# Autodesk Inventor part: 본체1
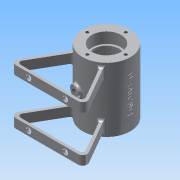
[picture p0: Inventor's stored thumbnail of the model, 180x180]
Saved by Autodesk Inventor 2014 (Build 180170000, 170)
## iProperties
Created: 2016-03
Part Number: 본체1
Material: 알루미늄 6061
Document SubType Name: Modeling
Designer: 406-16
Density: 2.71 g/cm^3
Appearance: 알루미늄 - 평지
Mass: 215.217 g
Surface Area: 337.503 cm^2
Volume: 79.416 cm^3
Author: 406-16
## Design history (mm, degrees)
sketch "스케치1"
  geometry: C1 r 26 at (0, 0); 1 further point
  constraints: 1 centre point, 1 coincident
  dimensions: "d0" = 52 diameter of C1
extrude "돌출1" new body sketch "스케치1" distance "d1" = 70; taper "d2" = 0 deg
sketch "스케치2"
  geometry: C1 r 26 at (0, 0) reference; C2 r 16 at (0, 0)
  constraints: 1 centre point, 1 coincident
  dimensions: "d3" = 32 diameter of C2
extrude "돌출2" cut sketch "스케치2" distance "d4" = 12; taper "d5" = 0 deg
sketch "스케치3"
  geometry: C1 r 16 at (0, 0) reference; C2 r 14 at (0, 0)
  constraints: 1 centre point, 1 coincident
  dimensions: "d6" = 28 diameter of C2
extrude "돌출3" cut sketch "스케치3" distance "d7" = 2; taper "d8" = 0 deg
sketch "스케치4"
  geometry: C1 r 26 at (0, 0) reference; C2 r 16 at (0, 0)
  constraints: 1 centre point, 1 coincident
  dimensions: "d9" = 32 diameter of C2
extrude "돌출4" cut sketch "스케치4" distance "d10" = 12; taper "d11" = 0 deg
sketch "스케치5"
  geometry: C1 r 16 at (0, 0) reference; C2 r 14 at (0, 0)
  constraints: 1 centre point, 1 coincident
  dimensions: "d12" = 28 diameter of C2
extrude "돌출5" cut sketch "스케치5" distance "d13" = 2; taper "d14" = 0 deg
node "작업 평면1"
sketch "스케치6"
  geometry: C1 r 21 at (0, 0); 1 further point
  constraints: 1 centre point, 1 coincident
  dimensions: "d16" = 42 diameter of C1
extrude "돌출6" cut sketch "스케치6" stored distance "d17" = 42; taper "d18" = 0 deg
node "작업 평면2"
sketch "스케치7"
  geometry: L1 (16.613, -20)-(38.264, -57.5); L2 (0, 0)-(0, -50.57); L3 (-16.613, -20)-(-38.264, -57.5); L4 (-33.934, -65)-(33.934, -65); L5 (14.015, -21.5)-(34.8, -57.5); L6 (32.202, -62)-(-32.202, -62); L7 (-34.8, -57.5)-(-14.015, -21.5); A1 r 5 centre (-33.934, -60) between (-38.264, -57.5) and (-33.934, -65); A2 r 5 centre (33.934, -60) between (33.934, -65) and (38.264, -57.5); A3 r 26 centre (0, 0) between (-16.613, -20) and (-14.183, -21.791); A4 r 26 centre (0, 0) between (14.183, -21.791) and (16.613, -20); A5 r 3 centre (-32.202, -59) between (-34.8, -57.5) and (-32.202, -62); A6 r 3 centre (32.202, -59) between (32.202, -62) and (34.8, -57.5); 3 further points
  constraints: 14 end point, 12 point on circle, 8 tangent, 6 centre point, 6 point on line, 2 symmetric about line, 1 coincident, 1 equal radius, 1 perpendicular, 1 vertical, 4 other
  dimensions: "d20" = 65 vertical distance of point (42.594, -65) point (0, 0); "d21" = 45 vertical distance of point (42.594, -65) L1.start; "d22" = 30 deg angle of L1 L2; "d23" = 3 distance between parallel lines of L7 L3; "d24" = 5 radius of A1; "d101" = 3 radius of A5; "d102" = 3 radius of A6; "d103" = 14.01517 distance from line of L5.start L2; "d104" = 29.67242 distance from line of L2.end L1; "d105" = 27.27499 distance from line of L7.end L1
extrude "돌출7" join sketch "스케치7" distance "d25" = 10; taper "d26" = 0 deg
node "작업 평면3"
sketch "스케치8"
  geometry: L1 (-26, 0)-(-26, -70) reference; L2 (-26, 0)-(26, 0) reference; C1 r 5 at (0, -35); 1 further point
  constraints: 1 centre point
  dimensions: "d28" = 10 diameter of C1; "d29" = 26 distance from line of C1.centre L1; "d30" = 35 distance from line of C1.centre L2
extrude "돌출8" join sketch "스케치8" stored distance "d31" = 3; taper "d32" = 0 deg
hole "구멍1" diameter "d35" = 5.188; stored, may be unused: countersink angle "d39" = 90 deg, drill point angle "d41" = 118 deg; dims "d33" = 10, "d34" = 10, "d36" = 20, "d37" = 4, "d38" = 2, "d40" = 25
sketch "스케치12"
  geometry: L1 (0, 21)-(0, 0); L2 (0, 0)-(21, 0); C1 r 26 at (0, 0) reference; A1 r 21 centre (0, 0) between (0, 21) and (21, 0)
  constraints: 4 end point, 2 point on circle, 1 centre point, 1 coincident, 1 perpendicular, 1 vertical
  dimensions: "d64" = 42 diameter of A1
hole "구멍3" sketch "스케치12" at (0, 21) diameter "d65" = 3.242; stored, may be unused: countersink angle "d69" = 90 deg, drill point angle "d71" = 118 deg; dims "d66" = 8, "d67" = 4, "d68" = 2, "d70" = 10
node "작업 평면5"
sketch "스케치13"
  geometry: L1 (26, 0)-(26, -70) reference; L2 (-26, 0)-(26, 0) reference; 2 further points
  constraints: 1 other
  dimensions: "d75" = 26 distance from line of point (0, -35) L1; "d76" = 35 distance from line of point (0, -35) L2
feature "엠보싱1" sketch "스케치13" dims "d77" = 0.5, "d78" = 0
sketch "스케치14"
  geometry: L1 (0, 0)-(-7.506, -28.012); L2 (0, 0)-(0, -34.845)
  constraints: 4 end point, 1 vertical
  dimensions: "d79" = 29 distance of L1.end L1.start; "d80" = 15 deg angle of L2 L1; "d81" = 9.01864 distance from line of L2.end L1
node "작업 평면6"
sketch "스케치15"
  geometry: L1 (-26, 35)-(-26, -35) reference; L2 (-26, 35)-(26, 35) reference; C1 r 6 at (0, 0); 1 further point
  constraints: 1 centre point
  dimensions: "d82" = 12 diameter of C1; "d84" = 26 distance from line of C1.centre L1; "d85" = 35 distance from line of C1.centre L2
extrude "돌출11" join sketch "스케치15" stored distance "d86" = 3; taper "d87" = 0 deg
hole "구멍4" diameter "d90" = 5.188; stored, may be unused: countersink angle "d94" = 90 deg, drill point angle "d96" = 118 deg; dims "d88" = 10, "d89" = 10, "d91" = 20, "d92" = 4, "d93" = 2, "d95" = 25
fillet "모깎기1" dims "d97" = 2
fillet "모깎기2" dims "d98" = 3
fillet "모깎기3" dims "d99" = 0.3
fillet "모깎기4" dims "d100" = 3
sketch "스케치16"
  geometry: L1 (0, 0)-(64.403, 0) reference; L2 (64.403, -10)-(0, -10) reference; C1 r 3 at (12.202, -5); C2 r 3 at (52.202, -5); 1 further point
  constraints: 2 centre point
  dimensions: "d106" = 6 diameter of C1; "d107" = 6 diameter of C2; "d108" = 20 horizontal distance of point (32.202, -15) C1.centre; "d109" = 40 distance of C2.centre C1.centre; "d110" = 5 distance from line of C1.centre L2; "d111" = 5 distance from line of L1 C2.centre
extrude "돌출12" cut sketch "스케치16" distance "d112" = 10; taper "d113" = 0 deg
node "솔리드1"
mirror "대칭1"
pattern_circular "원형 패턴1" dims angle "d73" = 360 deg
mirror "대칭3"
mirror "대칭4"
other parameters: "d15" = -35, "d27" = 29
